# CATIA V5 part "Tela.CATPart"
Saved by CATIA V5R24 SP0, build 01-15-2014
Part number: Tela
Bounding box of the stored display mesh (mm): x -3 to 3, y -25 to 25, z -32.5 to 32.5
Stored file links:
  C:\Users\Fatec\Downloads\Maquina componentes catia\Maquina componentes catia\Tela.CATPart
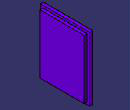
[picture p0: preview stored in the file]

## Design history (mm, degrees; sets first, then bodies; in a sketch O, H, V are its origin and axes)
Body1 (main body)
  Sketch1 on yz-plane, origin (0, 0, 0), H (0, 1, 0), V (0, 0, 1)
    line L1 (-22.5, 30) -> (22.5, 30)
    line L2 (22.5, 30) -> (22.5, -30)
    line L3 (22.5, -30) -> (-22.5, -30)
    line L4 (-22.5, -30) -> (-22.5, 30)
    length L3 = 45
    length L2 = 60
    horizontal: L1 H, L3 H
    vertical: L2 V, L4 V
    symmetry: L3 L1 H, L4 L2 V
  Pad1: profile Sketch1, direction (1, 0, 0), length 3
  Sketch2 on start face of Pad1, origin (0, 0, 0), H (0, -1, 0), V (0, 0, 1)
    line L1 (-25, 32.5) -> (25, 32.5)
    line L2 (25, 32.5) -> (25, -32.5)
    line L3 (25, -32.5) -> (-25, -32.5)
    line L4 (-25, -32.5) -> (-25, 32.5)
    length L3 = 50
    length L2 = 65
    horizontal: L1 H, L3 H
    vertical: L2 V, L4 V
    symmetry: L3 L1 H, L4 L2 V
  Pad2: profile Sketch2, direction (-1, 0, 0), length 3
